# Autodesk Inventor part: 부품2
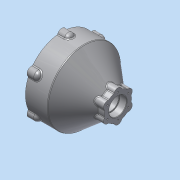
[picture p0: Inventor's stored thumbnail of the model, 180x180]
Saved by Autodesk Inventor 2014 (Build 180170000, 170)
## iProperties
Created: 2026-05
Part Number: 부품2
Material: 알루미늄 6061
Document SubType Name: Modeling
Designer: dg
Density: 2.71 g/cm^3
Appearance: 알루미늄 - 평지
Mass: 1987.95 g
Surface Area: 1180.02 cm^2
Volume: 733.561 cm^3
Author: dg
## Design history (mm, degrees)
sketch "스케치1"
  geometry: L1 (0, 0)-(-63, 0); L2 (-63, 0)-(-63, 82); L3 (-63, 82)-(-13, 82); L4 (-13, 82)-(48.375, 30.5); L5 (48.375, 30.5)-(63, 30.5); L6 (63, 30.5)-(63, 0); L7 (63, 0)-(0, 0); L8 (-63, 0)-(63, 0)
  constraints: 16 end point, 3 parallel, 2 collinear, 1 horizontal, 1 perpendicular
  dimensions: "d0" = 61 diameter of L5 L7; "d1" = 164 diameter of L3 L1; "d2" = 40 deg angle of L3 L4; "d3" = 50 distance of L2.end L3.end; "d4" = 126 distance between parallel lines of L2 L6; "d5" = 63 distance from line of L2 L1.start
revolve "회전1" sketch "스케치1" stored, may be unused: angle "d6" = 90 deg
sketch "스케치6" dims "d73" = 54
  geometry: L1 (0, 0)-(0, 86.548); L2 (0, 0)-(28.257, 48.942); C1 r 30.5 at (0, 0) reference; C2 r 9 at (13.5, 23.383)
  constraints: 4 end point, 1 centre point, 1 coincident, 1 point on line, 1 vertical, 3 other
  dimensions: "d74" = 30 deg angle of L1 L2; "d75" = 18 diameter of C2
extrude "돌출2" join sketch "스케치6" stored distance "d76" = 20; taper "d77" = 0 deg
sketch "스케치11" dims "d109" = 158
  geometry: L1 (0, 0)-(0, 114.814); L2 (0, 0)-(60.185, 104.244); C1 r 82 at (0, 0) reference; C2 r 10 at (39.5, 68.416)
  constraints: 4 end point, 1 centre point, 1 coincident, 1 point on line, 1 vertical, 3 other
  dimensions: "d110" = 30 deg angle of L1 L2; "d111" = 20 diameter of C2
extrude "돌출4" join sketch "스케치11" distance "d112" = 25; taper "d113" = 0 deg
fillet "모깎기13" dims "d129" = 10
fillet "모깎기14" dims "d130" = 3
sketch "스케치3"
  geometry: L1 (0, 0)-(-63, 0); L2 (0, 0)-(63, 0); L3 (63, 0)-(47, 0); L4 (47, 0)-(47, 20); L5 (47, 20)-(63, 20); L6 (63, 20)-(63, 0); L7 (47, 0)-(31, 0); L8 (31, 0)-(31, 17.5); L9 (31, 17.5)-(47, 17.5); L10 (47, 17.5)-(47, 0); L11 (31, 0)-(19, 0); L12 (19, 0)-(19, 20); L13 (19, 20)-(31, 20); L14 (31, 20)-(31, 0); L15 (19, 0)-(15, 0); L16 (15, 0)-(15, 37); L17 (15, 37)-(19, 37); L18 (19, 37)-(19, 0); L19 (15, 0)-(-1, 0); L20 (-1, 0)-(-1, 40); L21 (-1, 40)-(15, 40); L22 (15, 40)-(15, 0); L23 (-1, 0)-(-21, 0); L24 (-21, 0)-(-21, 56); L25 (-21, 56)-(-1, 56); L26 (-1, 56)-(-1, 0); L27 (-21, 0)-(-26, 0); L28 (-26, 0)-(-26, 68); L29 (-26, 68)-(-21, 68); L30 (-21, 68)-(-21, 0); L31 (-26, 0)-(-63, 0); L32 (-63, 0)-(-63, 73); L33 (-63, 73)-(-26, 73); L34 (-26, 73)-(-26, 0)
  constraints: 68 end point, 17 equal length, 9 horizontal, 8 perpendicular
  dimensions: "d14" = 63 distance of L1.start L1.end; "d15" = 63 distance of L1.start L2.end; "d16" = 146 diameter of L33 L2; "d17" = 136 diameter of L29 L2; "d18" = 37 distance between parallel lines of L32 L34; "d19" = 5 distance between parallel lines of L28 L30; "d20" = 25 distance between parallel lines of L20 L28; "d21" = 112 diameter of L25 L2; "d22" = 80 diameter of L21 L2; "d23" = 16 distance between parallel lines of L6 L4; "d24" = 40 diameter of L5 L2; "d25" = 35 diameter of L9 L2; "d26" = 12 distance between parallel lines of L12 L8; "d27" = 40 diameter of L13 L2; "d28" = 16 distance between parallel lines of L26 L22; "d29" = 20 distance between parallel lines of L18 L20; "d30" = 74 diameter of L17 L2
revolve "회전2" sketch "스케치3" stored, may be unused: angle "d31" = 90 deg
chamfer "모따기1" distance "d32" = 1; stored, may be unused: second distance "d33" = 2, angle "d34" = 45 deg
fillet "모깎기1" dims "d35" = 3
chamfer "모따기2" distance "d36" = 1; stored, may be unused: second distance "d37" = 2, angle "d38" = 45 deg
fillet "모깎기2" dims "d39" = 3
chamfer "모따기3" distance "d40" = 1; stored, may be unused: second distance "d41" = 2, angle "d42" = 45 deg
fillet "모깎기3" dims "d43" = 1
chamfer "모따기4" distance "d44" = 1; stored, may be unused: second distance "d45" = 2, angle "d46" = 45 deg
fillet "모깎기4" dims "d47" = 3
chamfer "모따기5" distance "d48" = 1; stored, may be unused: second distance "d49" = 2, angle "d50" = 45 deg
fillet "모깎기5" dims "d51" = 0.6
fillet "모깎기6" dims "d52" = 3
fillet "모깎기7" dims "d53" = 3
sketch "스케치5" dims "d61" = 124
  geometry: L1 (0, 0)-(0, 104.094); L2 (0, 0)-(53.078, 91.934); C1 r 68 at (0, 0) reference; 1 further point
  constraints: 4 end point, 1 coincident, 1 point on line, 1 vertical, 3 other
  dimensions: "d62" = 30 deg angle of L1 L2
hole "구멍2" sketch "스케치5" at (31, 53.694) diameter "d63" = 3.242; stored, may be unused: countersink angle "d67" = 90 deg, drill point angle "d69" = 118 deg; dims "d64" = 8, "d65" = 4, "d66" = 2, "d68" = 10
sketch "스케치7"
  geometry: A1 r 9 centre (40.5, 23.383) between (49.165, 20.951) and (34.062, 29.671) reference; A2 r 9 centre (13.5, 23.383) between (19.938, 29.671) and (4.835, 20.951) reference; A3 r 9 centre (0, 0) between (-2.227, 8.72) and (-2.227, -8.72) reference; A4 r 9 centre (13.5, -23.383) between (4.835, -20.951) and (19.938, -29.671) reference; A5 r 9 centre (40.5, -23.383) between (34.062, -29.671) and (49.165, -20.951) reference; A6 r 9 centre (54, 0) between (56.227, -8.72) and (56.227, 8.72) reference; 6 further points
  constraints: 6 coincident
hole "구멍3" sketch "스케치7" at (13.5, 23.383), (0, 0), (40.5, 23.383), (54, 0), (40.5, -23.383), (13.5, -23.383) diameter "d81" = 3.242; stored, may be unused: countersink angle "d85" = 90 deg, drill point angle "d87" = 118 deg; dims "d82" = 8, "d83" = 4, "d84" = 2, "d86" = 10
fillet "모깎기8" dims "d88" = 3
sketch "스케치14"
  geometry: A1 r 10 centre (0, 0) between (-3.968, 9.179) and (-3.968, -9.179) reference; A2 r 10 centre (39.5, -68.416) between (29.567, -67.263) and (45.465, -76.442) reference; A3 r 10 centre (118.5, -68.416) between (112.535, -76.442) and (128.433, -67.263) reference; A4 r 10 centre (158, 0) between (161.968, -9.179) and (161.968, 9.179) reference; A5 r 10 centre (118.5, 68.416) between (128.433, 67.263) and (112.535, 76.442) reference; A6 r 10 centre (39.5, 68.416) between (45.465, 76.442) and (29.567, 67.263) reference; 6 further points
  constraints: 6 coincident
hole "구멍6" sketch "스케치14" at (39.5, 68.416), (0, 0), (118.5, 68.416), (158, 0), (118.5, -68.416), (39.5, -68.416) diameter "d134" = 4.917; stored, may be unused: countersink angle "d138" = 90 deg, drill point angle "d140" = 118 deg; dims "d135" = 12, "d136" = 4, "d137" = 2, "d139" = 14
node "작업 평면3"
sketch "스케치15"
  geometry: L1 (25, 30.625)-(25, -30.625) reference; 2 further points
  constraints: 1 horizontal alignment, 1 other
  dimensions: "d141" = 20 distance from line of L1 point (5, 0)
feature "엠보싱3" sketch "스케치15" dims "d14" = 63, "d15" = 63, "d16" = 146, "d17" = 136, "d18" = 37, "d19" = 5, "d20" = 25, "d21" = 112, "d22" = 80, "d23" = 16, "d24" = 40, "d25" = 35, "d26" = 12, "d27" = 40, "d28" = 16, "d29" = 20, "d30" = 74, "d142" = 0.5, "d143" = 0
node "솔리드1"
pattern_circular "원형 패턴6" dims "d132" = 360 deg
pattern_circular "원형 패턴2" dims angle "d71" = 360 deg
pattern_circular "원형 패턴3" dims angle "d79" = 360 deg
